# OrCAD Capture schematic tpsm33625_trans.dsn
size B; title: TPSM33625 Steady State; rev: A; note: Datasheet: SLVSCB1 EVM: SLVUCG3
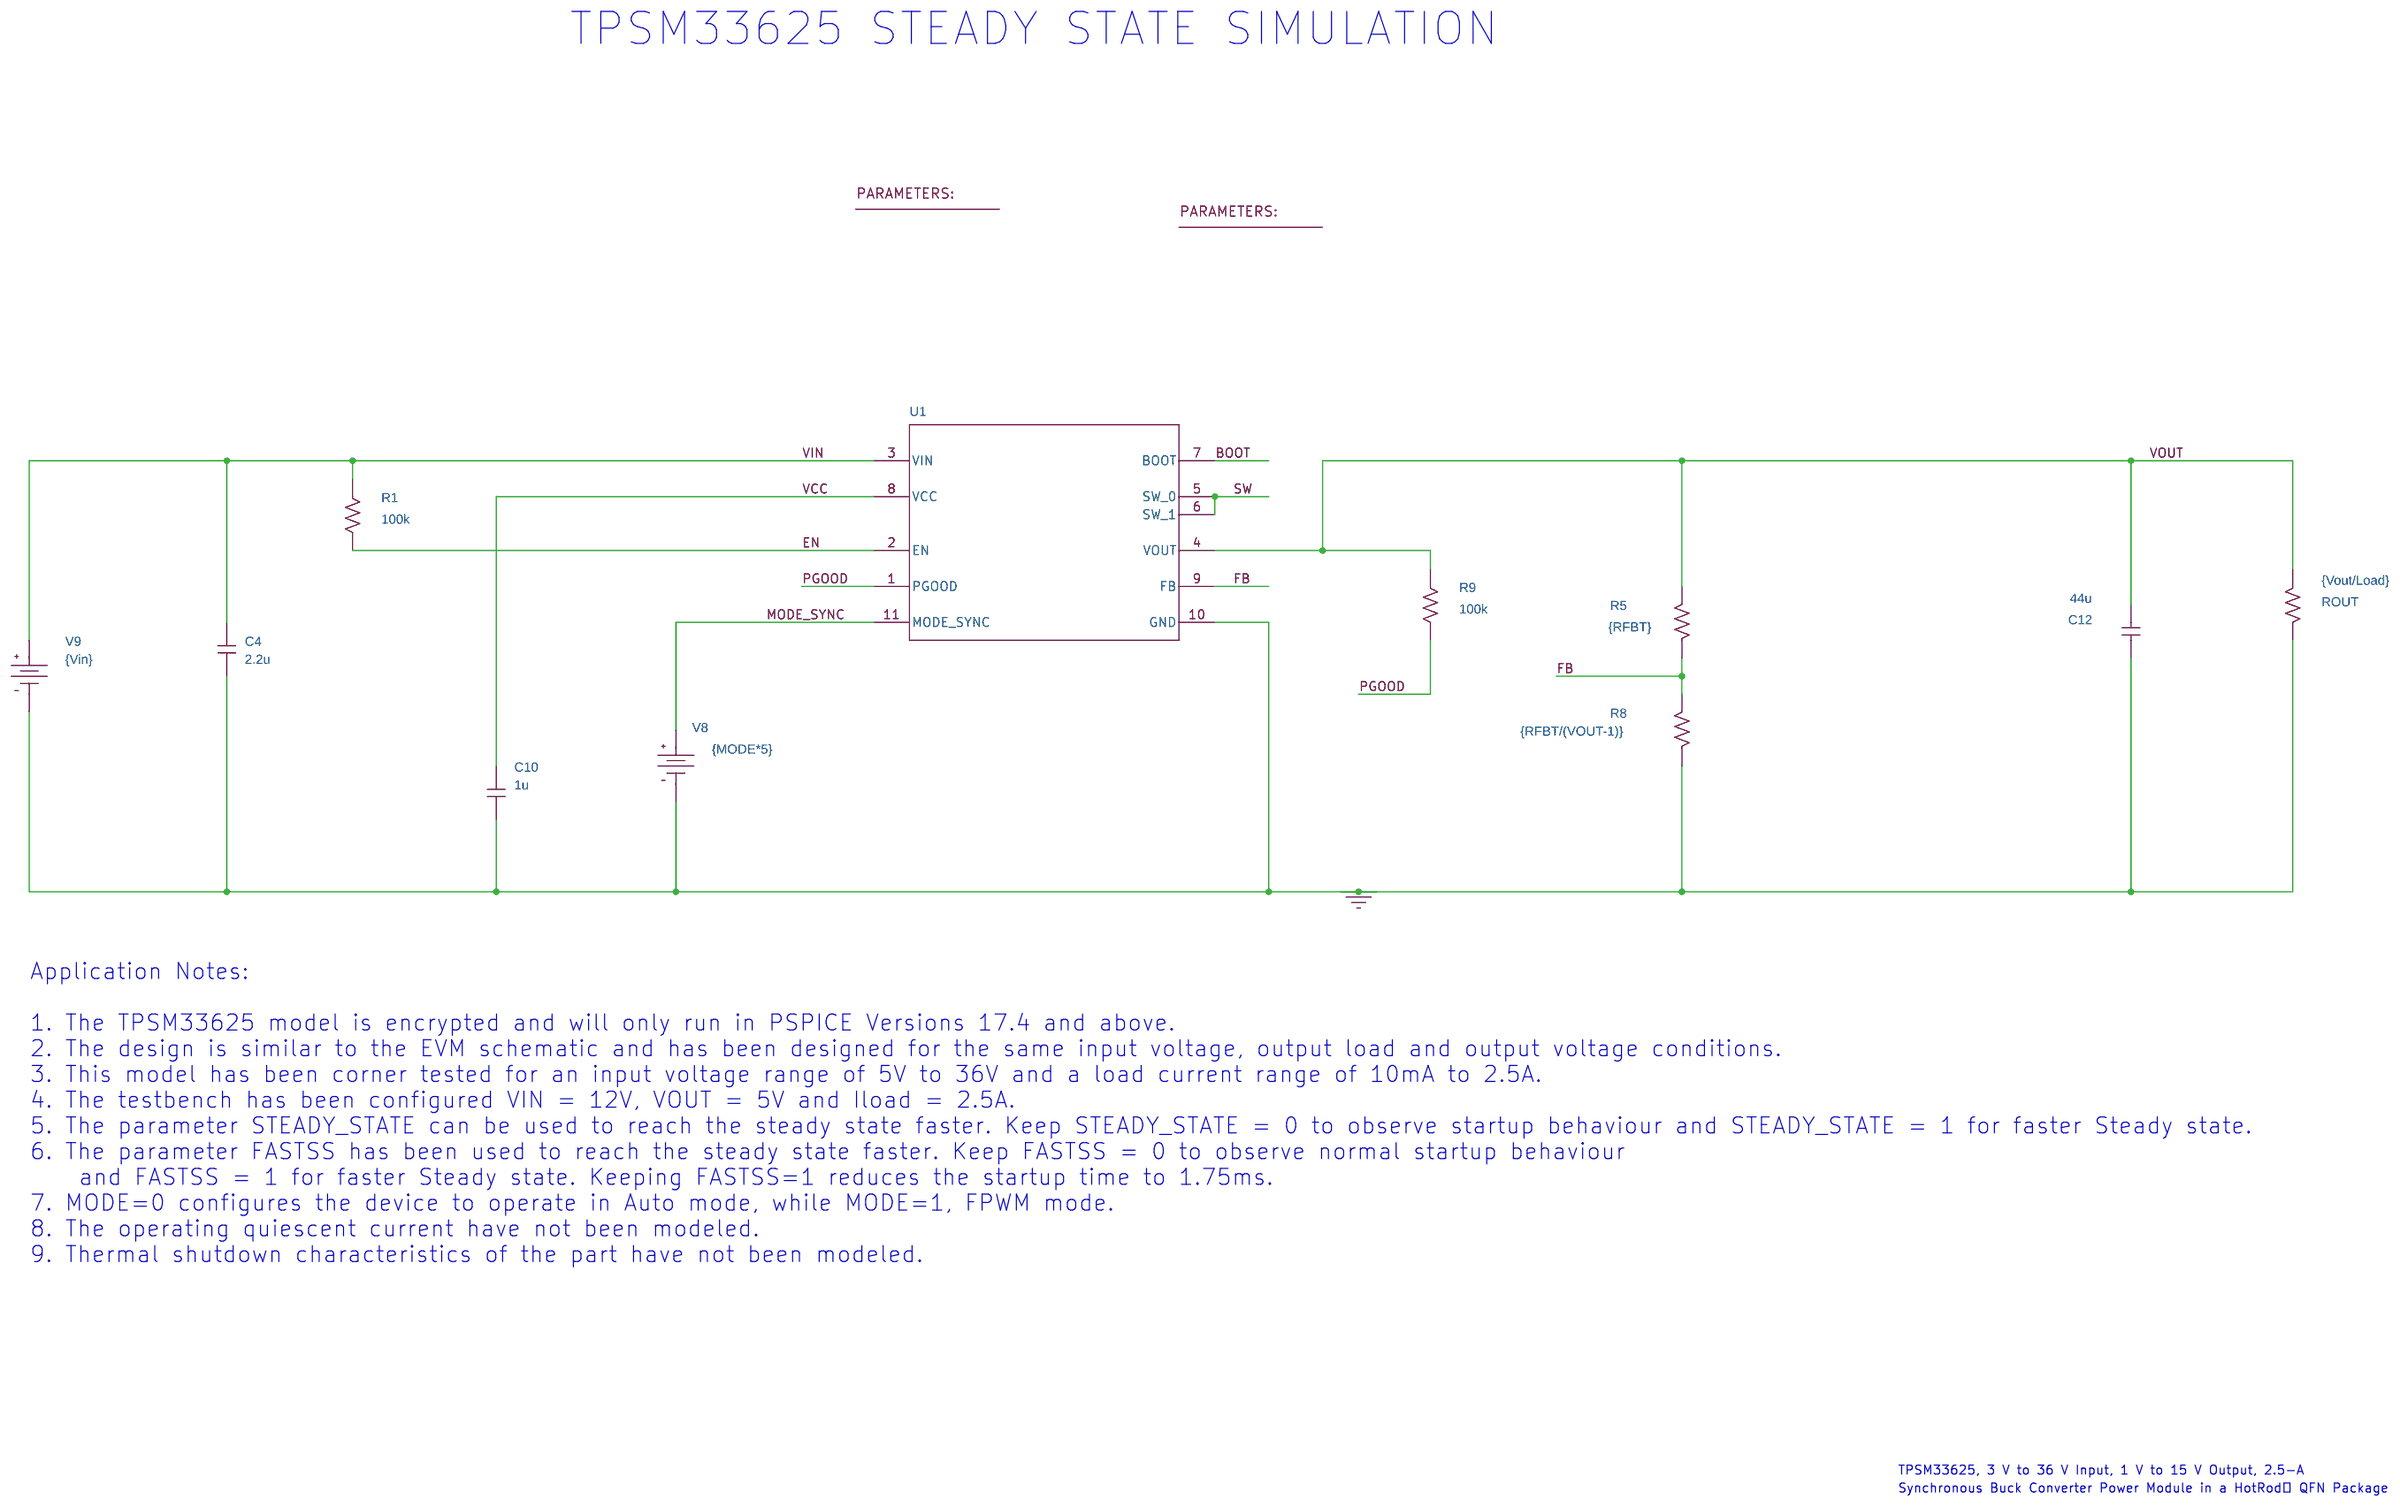
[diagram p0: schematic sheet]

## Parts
1  PARAM
4  PARAM
C4  2.2u  [RAD/CK05]
C10  1u  [RAD/CK05]
C12  44u  [RAD/CK05]
R1  100k  [AX/RC05]
R5  {RFBT}  [AX/RC05]
R8  {RFBT/(VOUT-1)}  [AX/RC05]
R9  100k  [AX/RC05]
ROUT  {Vout/Load}  [RC05]
U1  Value  [RDN0011A-MFG]
V8  VDC
V9  VDC

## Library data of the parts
1 = PARAM: MODE: 0
4 = PARAM: Load: 2.5; PW_VIN: 5m; TD_VIN: 10u; TF_VIN: 100n; TR_VIN: 100n; VIN1: {STEADY_STATE*VIN2}; VIN2: 13.5; Vin: 12; rfbt: 100K; vout: 5
C4 = C
C10 = C: IC: {STEADY_STATE*3.5}
C12 = C: IC: {STEADY_STATE*Vout}
R1 R5 R8 R9 ROUT = R
U1 = TPSM33625RDN_TRANS: FASTSS: {FASTSS}; STEADY_STATE: {STEADY_STATE}
V8 = VDC: DC: {MODE*5}
V9 = VDC: DC: {Vin}

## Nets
VCC: C10.1 U1.8(VCC)
VIN: C4.2 R1.1 U1.3(VIN) V9.0(+)
0: C4.1 C10.2 C12.2 R8.1 ROUT.2 U1.10(GND) V8.1(-) V9.1(-)
BOOT: U1.7(BOOT)
EN: R1.2 U1.2(EN)
FB: R5.1 R8.2 U1.9(FB)
MODE_SYNC: U1.11(MODE_SYNC) V8.0(+)
PGOOD: R9.2 U1.1(PGOOD)
SW: U1.5(SW_0) U1.6(SW_1)
VOUT: C12.1 R5.2 R9.1 ROUT.1 U1.4(VOUT)

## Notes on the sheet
- TPSM33625 STEADY STATE SIMULATION
- Application Notes:
  1. The TPSM33625 model is encrypted and will only run in PSPICE Versions 17.4 and above.
  2. The design is similar to the EVM schematic and has been designed for the same input voltage, output load and output voltage conditions.
  3. This model has been corner tested for an input voltage range of 5V to 36V and a load current range of 10mA to 2.5A.
  4. The testbench has been configured VIN = 12V, VOUT = 5V and Iload = 2.5A.
  5. The parameter STEADY_STATE can be used to reach the steady state faster. Keep STEADY_STATE = 0 to observe startup behaviour and STEADY_STATE = 1 for faster Steady state.
  6. The parameter FASTSS has been used to reach the steady state faster. Keep FASTSS = 0 to observe normal startup behaviour
      and FASTSS = 1 for faster Steady state. Keeping FASTSS=1 reduces the startup time to 1.75ms.
  7. MODE=0 configures the device to operate in Auto mode, while MODE=1, FPWM mode.
  8. The operating quiescent current have not been modeled.
  9. Thermal shutdown characteristics of the part have not been modeled.
- Synchronous Buck Converter Power Module in a HotRod™ QFN Package
- TPSM33625, 3 V to 36 V Input, 1 V to 15 V Output, 2.5-A
